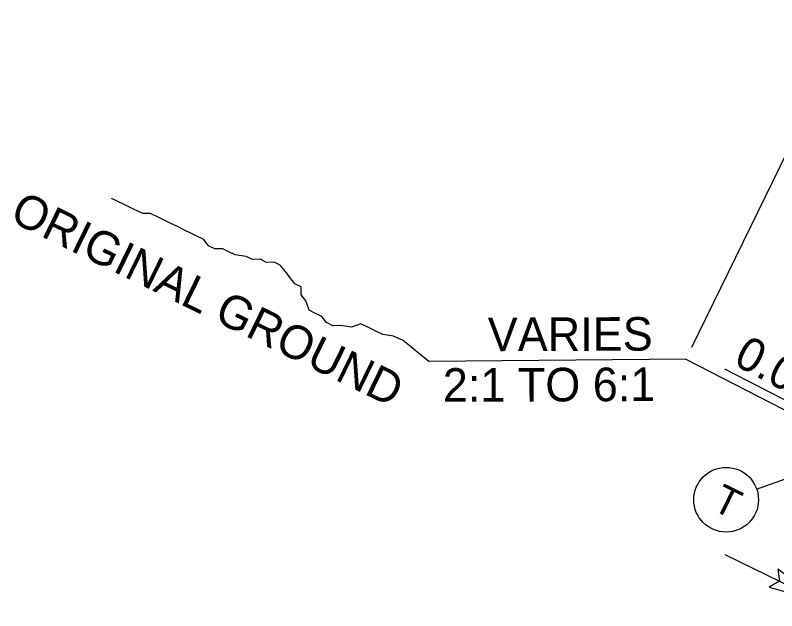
# Model space of a CAD drawing. Extents: x 1518247 to 1523638, y 635234 to 639927.
# Drawn here: x 1522516.8 to 1522742.5, y 637095.4 to 637272.1 of the extents above; entities that cross this region are included whole.
import ezdxf

# ---------------------------------------------------------------- set-up
doc = ezdxf.new("R2010")
doc.units = 0
for name, color, linetype in [('Prop Dimension', 7, 'Continuous'), ('Prop Shade Light', 7, 'Continuous'), ('Typical Berm CELL', 7, 'Continuous'), ('Typical Berm Information CELL', 7, 'Continuous'), ('Typical Hinge Slope Arterial CELL', 7, 'Continuous'), ('Typical Hinge Slope Interstate CELL', 7, 'Continuous'), ('Typical ID Circle CELL', 7, 'Continuous'), ('Typical Text ID Circle CELL', 7, 'Continuous')]:
    doc.layers.add(name, color=color, linetype=linetype)

# ---------------------------------------------------------------- blocks, each defined once
blk = doc.blocks.new('TERMINATOR')
at = {"layer": 'Prop Shade Light'}
blk.add_lwpolyline([(-0.4687, 0.0807), (0, 0), (-0.4713, -0.0833), (-0.4114, 0)], close=True, dxfattribs=at)

msp = doc.modelspace()

# ---------------------------------------------------------------- linework, layer by layer
at = {"layer": 'Prop Dimension'}
for p, q in [((1522717.34, 637173.63), (1522765.38, 637272.05)), ((1522755.85, 637098.06), (1522727.21, 637112.05))]:
    msp.add_line(p, q, dxfattribs=at)
at = {"layer": 'Typical Berm CELL'}
msp.add_line((1522715.59, 637170.05), (1522782.95, 637135.4), dxfattribs=at)
at = {"layer": 'Typical Berm Information CELL'}
msp.add_line((1522761.64, 637149.3), (1522727.1, 637167.06), dxfattribs=at)
at = {"layer": 'Typical Hinge Slope Interstate CELL'}
msp.add_line((1522715.59, 637170.05), (1522639.36, 637169.32), dxfattribs=at)
msp.add_lwpolyline([(1522639.36, 637169.32), (1522631.73, 637175.54), (1522628.94, 637176.9), (1522625.7, 637177.34), (1522623.85, 637178.25), (1522621.05, 637179.61), (1522619.2, 637180.52), (1522616.43, 637179.56), (1522613.18, 637179.99), (1522610.87, 637179.97), (1522609.01, 637180.88), (1522607.61, 637182.72), (1522605.75, 637183.62), (1522603.89, 637184.53), (1522602.94, 637187.3), (1522601.54, 637189.14), (1522601.51, 637191.45), (1522599.65, 637192.36), (1522598.25, 637194.19), (1522596.84, 637196.03), (1522595.44, 637197.87), (1522593.58, 637198.78), (1522591.27, 637198.75), (1522589.41, 637199.66), (1522587.09, 637199.64), (1522585.24, 637200.54), (1522581.99, 637200.98), (1522580.13, 637201.89), (1522578.27, 637202.79), (1522575.96, 637202.77), (1522574.1, 637203.68), (1522572.7, 637205.52), (1522570.84, 637206.42), (1522568.98, 637207.33), (1522567.12, 637208.24), (1522565.26, 637209.15), (1522562.47, 637210.51), (1522559.69, 637211.87), (1522556.9, 637213.23), (1522554.58, 637213.2), (1522551.8, 637214.56), (1522549.01, 637215.93), (1522545.29, 637217.74)], dxfattribs=at)
at = {"layer": 'Typical ID Circle CELL'}
msp.add_line((1522736.55, 637131.53), (1522759.92, 637139.77), dxfattribs=at)
msp.add_circle((1522727.51, 637128.35), 9.59, dxfattribs=at)

# ---------------------------------------------------------------- block references
at = {"layer": 'Prop Dimension', "xscale": 33.82820784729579, "yscale": -36.41552511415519, "rotation": -26.020730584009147}
msp.add_blockref('TERMINATOR', (1522755.85, 637098.06), dxfattribs=at)

# ---------------------------------------------------------------- texts
at = {"layer": 'Typical Berm Information CELL'}
msp.add_text('0.02', height=9.969, rotation=332.1708, dxfattribs=at).set_placement((1522729.3, 637168.63))
at = {"layer": 'Typical Hinge Slope Arterial CELL'}
for s, height, rotation, p in [('ORIGINAL GROUND', 9.9687, 333.9793, (1522514.73, 637211.19)), ('VARIES', 9.969, 0.2071, (1522656.86, 637172.4)), ('2:1 TO 6:1', 9.969, 0.2071, (1522643.54, 637157.39))]:
    msp.add_text(s, height=height, rotation=rotation, dxfattribs=at).set_placement(p)
at = {"layer": 'Typical Text ID Circle CELL'}
msp.add_text('T', height=8.58, rotation=333.9793, dxfattribs=at).set_placement((1522722.96, 637125.55))

doc.saveas('drawing.dxf')
